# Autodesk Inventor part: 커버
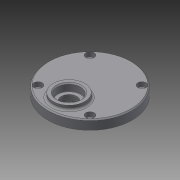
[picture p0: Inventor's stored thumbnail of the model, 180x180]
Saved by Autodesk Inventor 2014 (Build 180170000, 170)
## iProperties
Created: 2015-07
Part Number: 커버
Material: Generic
Document SubType Name: Modeling
Designer: Administrator
Mass: 42.0316 g
Surface Area: 144.874 cm^2
Volume: 42.0316 cm^3
Density: 1 g/cm^3
Appearance: Default
Author: Administrator
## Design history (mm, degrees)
sketch "스케치1"
  geometry: C1 r 40 at (0, 0); 1 further point
  constraints: 1 centre point, 1 coincident
  dimensions: "d0" = 80 diameter of C1
extrude "돌출1" new body sketch "스케치1" distance "d1" = 9; taper "d2" = 0 deg
sketch "스케치2"
  geometry: C1 r 40 at (0, 0) reference; C2 r 14 at (0, 11); C3 r 14 at (0, -20)
  constraints: 2 centre point, 2 vertical alignment
  dimensions: "d3" = 28 diameter of C2; "d4" = 28 diameter of C3; "d5" = 11 distance of C1.centre C2.centre; "d6" = 20 distance of C3.centre C1.centre
extrude "돌출2" join sketch "스케치2" distance "d7" = 3; taper "d8" = 0 deg
sketch "스케치3"
  geometry: C1 r 14 at (0, 0) reference; C2 r 14 at (0, -31) reference; C3 r 11 at (0, 0); C4 r 11 at (0, -31); 1 further point
  constraints: 2 centre point, 2 coincident
  dimensions: "d9" = 22 diameter of C3; "d10" = 22 diameter of C4
extrude "돌출3" cut sketch "스케치3" distance "d11" = 7; taper "d12" = 0 deg
sketch "스케치4"
  geometry: C1 r 9 at (0, 0); 2 further points
  constraints: 1 centre point, 1 coincident, 1 vertical alignment
  dimensions: "d13" = 18 diameter of C1
extrude "돌출4" cut sketch "스케치4" distance "d14" = 1; taper "d15" = 0 deg
sketch "스케치5"
  geometry: C1 r 11 at (0, 0) reference; C2 r 7.5 at (0, 0); 1 further point
  constraints: 1 centre point, 1 coincident
  dimensions: "d16" = 15 diameter of C2
extrude "돌출5" cut sketch "스케치5" stored distance "d17" = 1; taper "d18" = 0 deg
sketch "스케치6"
  geometry: C1 r 7.5 at (0, -20) reference; C2 r 15 at (0, -20)
  constraints: 1 centre point, 1 coincident
  dimensions: "d19" = 30 diameter of C2
extrude "돌출6" join sketch "스케치6" distance "d20" = 4; taper "d21" = 0 deg
sketch "스케치7"
  geometry: C1 r 7.5 at (0, 0) reference; C2 r 15 at (0, 0) reference; C3 r 11 at (0, 0); 1 further point
  constraints: 1 centre point, 1 coincident
  dimensions: "d22" = 22 diameter of C3
extrude "돌출7" cut sketch "스케치7" distance "d23" = 7; taper "d24" = 0 deg
sketch "스케치8"
  geometry: L1 (-24.749, 24.749)-(0, 0); L2 (0, 0)-(0, 35); C1 r 40 at (0, 0) reference; C2 r 4 at (-24.749, 24.749); A1 r 35 centre (0, 0) between (-24.749, 24.749) and (0, 35)
  constraints: 4 end point, 2 centre point, 2 point on circle, 1 coincident, 1 vertical
  dimensions: "d25" = 70 diameter of A1; "d26" = 8 diameter of C2; "d27" = 45 deg angle of L2 L1
extrude "돌출8" cut sketch "스케치8" distance "d28" = 4.4; taper "d29" = 0 deg
sketch "스케치9"
  geometry: C1 r 4 at (0, 0) reference; C2 r 2.25 at (0, 0); 1 further point
  constraints: 1 centre point, 1 coincident
  dimensions: "d30" = 4.5 diameter of C2
extrude "돌출9" cut sketch "스케치9" stored distance "d31" = 4.4; taper "d32" = 0 deg
chamfer "모따기1" distance "d36" = 1; stored, may be unused: second distance "d37" = 2, angle "d38" = 45 deg
fillet "모깎기1" dims "d39" = 2
fillet "모깎기2" dims "d40" = 2
fillet "모깎기3" dims "d41" = 0.3
chamfer "모따기2" distance "d42" = 1; stored, may be unused: second distance "d43" = 2, angle "d44" = 45 deg
node "솔리드1"
pattern_circular "원형 패턴1" dims angle "d34" = 360 deg
node "투영된 루프1"
